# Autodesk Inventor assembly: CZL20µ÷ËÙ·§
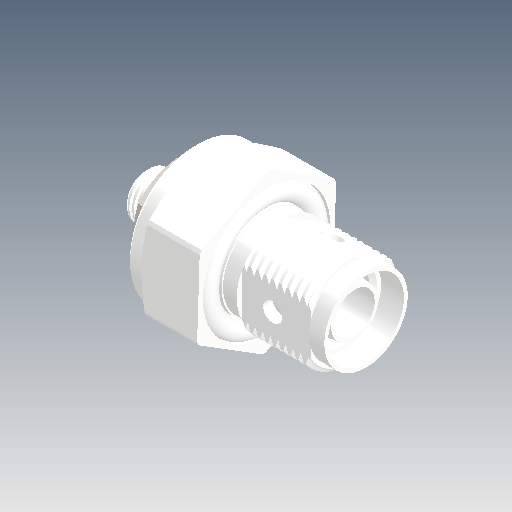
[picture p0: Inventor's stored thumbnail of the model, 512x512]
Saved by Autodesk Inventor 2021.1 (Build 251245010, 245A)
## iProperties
Created: 2021-05
Part Number: CZL20µ÷ËÙ·§
Document SubType Name: Assembly
Designer: user
Author: user
Revision Number: ÈÎºÎ
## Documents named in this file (4)
- D:\Vault_2016\Projekty\Clamptek\Hydraulic\CHLC\CHLC-50\Inventor\CHLC-FAMT50R\CZL20µ÷ËÙ·§.iam
- D:\Vault_2016\Projekty\Clamptek\Hydraulic\CHLC\CHLC-50\Inventor\CHLC-FAMT50R\20·§Ìå.ipt
- D:\Vault_2016\Projekty\Clamptek\Hydraulic\CHLC\CHLC-50\Inventor\CHLC-FAMT50R\20µ÷ËÙ¸Ë.ipt
- D:\Vault_2016\Projekty\Clamptek\Hydraulic\CHLC\CHLC-50\Inventor\CHLC-FAMT50R\hex thin nuts-grades ab-chamfered gb(GB_FASTENER_NUT_STNAB M6-S).ipt
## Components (3 placed, 3 different names)
1. 20·§Ìå_20
2. 20µ÷ËÙ¸Ë_21
3. hex thin nuts-grades ab-chamfered gb(GB_FASTENER_NUT_STNAB M6-S)_22
